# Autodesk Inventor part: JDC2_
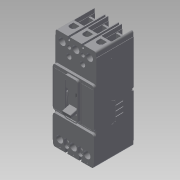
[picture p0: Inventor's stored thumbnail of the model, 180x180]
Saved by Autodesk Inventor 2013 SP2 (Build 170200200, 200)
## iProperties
Created: 2014-08
Part Number: JDC2_
Material: Generic
Document SubType Name: Modeling
Designer: DM/JS
Density: 1 g/cm^3
Description: TYPE JDC THERMAL MAGNETIC CIRCUIT BREAKERS TWO POLE, SERIES C
MXEDIT: false
MXINVTNRV: INV Versioned Component|JDC2_|004.0
Author: DM/JS
Revision Number: 004
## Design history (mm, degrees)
derived "JD2_.iam"
node "L1"
node "L2"
node "T1"
node "T2"
sketch "Sketch1"
  geometry: C1 r 8.738 at (5.715, 1.905) reference; C2 r 8.738 at (75.565, 1.905) reference; C3 r 10.795 at (5.715, 213.843) reference; C4 r 10.795 at (5.715, 213.843) reference; C5 r 10.795 at (75.565, 213.843) reference; 1 further point
extrude "Extrusion1" cut sketch "Sketch1" stored distance "d1" = 25.4; taper "d2" = 0 deg
sketch "Sketch2"
  geometry: L1 (17.475, 0)-(0, 0) reference; L2 (0, 0)-(0, -23.012) reference; L3 (0, -23.012)-(17.475, -23.012) reference; L4 (17.475, -23.012)-(17.475, 0) reference; L5 (4.572, -8.738)-(4.572, -11.913) reference; L6 (12.903, -11.913)-(12.903, -8.738) reference; L7 (52.4, 0)-(34.925, 0) reference; L8 (34.925, 0)-(34.925, -23.012) reference; L9 (34.925, -23.012)-(52.4, -23.012) reference; L10 (52.4, -23.012)-(52.4, 0) reference; L11 (39.497, -8.738)-(39.497, -11.913) reference; L12 (47.828, -11.913)-(47.828, -8.738) reference; L13 (87.325, 0)-(69.85, 0) reference; L14 (69.85, 0)-(69.85, -23.012) reference; L15 (69.85, -23.012)-(87.325, -23.012) reference; L16 (87.325, -23.012)-(87.325, 0) reference; L17 (74.422, -8.738)-(74.422, -11.913) reference; L18 (82.753, -11.913)-(82.753, -8.738) reference; A1 r 4.166 centre (8.738, -8.738) between (12.903, -8.738) and (4.572, -8.738) reference; A2 r 4.166 centre (8.738, -11.913) between (4.572, -11.913) and (12.903, -11.913) reference; A3 r 4.166 centre (43.663, -8.738) between (47.828, -8.738) and (39.497, -8.738) reference; A4 r 4.166 centre (43.663, -11.913) between (39.497, -11.913) and (47.828, -11.913) reference; A5 r 4.166 centre (78.588, -8.738) between (82.753, -8.738) and (74.422, -8.738) reference; A6 r 4.166 centre (78.588, -11.913) between (74.422, -11.913) and (82.753, -11.913) reference; 1 further point
extrude "Extrusion2" join sketch "Sketch2" stored distance "d3" = 25.4; taper "d4" = 0 deg
body "Solid1"
node "JD2_.ipt:1"
node "Projected Loop1"
node "Projected Loop2"
node "Projected Loop3"
node "Projected Loop4"
